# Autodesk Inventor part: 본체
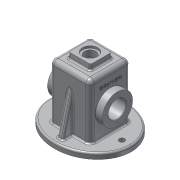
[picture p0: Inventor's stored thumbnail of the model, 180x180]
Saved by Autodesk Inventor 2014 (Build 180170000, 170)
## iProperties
Created: 2017-07
Part Number: 본체
Material: Aluminum 6061
Document SubType Name: Modeling
Designer: user
Density: 2.71 g/cm^3
Appearance: Aluminum - Flat
Mass: 887.783 g
Surface Area: 995.339 cm^2
Volume: 327.595 cm^3
Author: user
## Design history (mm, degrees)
sketch "Sketch1" dims "d0" = 75, "d1" = 65
  geometry: 2 further points; 1 other entity
  constraints: 1 coincident, 2 other
extrude "Extrusion1" new body sketch "Sketch1" distance "d2" = 10; taper "d3" = 0 deg
sketch "Sketch2"
  geometry: L1 (37, -37)-(-37, -37); L2 (-37, -37)-(-37, 37); L3 (-37, 37)-(37, 37); L4 (37, 37)-(37, -37); L5 (37, -37)-(-37, 37); L6 (-37, -37)-(37, 37); 1 further point; 1 other entity
  constraints: 12 end point, 2 midpoint, 2 parallel, 1 horizontal, 1 perpendicular, 1 other
  dimensions: "d4" = 74 distance of L2.end L3.end; "d5" = 74 distance of L1.end L2.end
extrude "Extrusion2" join sketch "Sketch2" distance "d6" = 100; taper "d7" = 0 deg
sketch "Sketch3"
  geometry: L1 (37, 82.194)-(55, 10); L2 (37, 10)-(37, 110) reference; L3 (65, 10)-(-65, 10) reference; L4 (37, 82.194)-(37, 10); L5 (37, 10)-(55, 10); L6 (65, 10)-(65, 80); 1 further point
  constraints: 8 end point, 1 perpendicular
  dimensions: "d8" = 0 distance from line of L2 L1.start; "d9" = 0 distance from line of L3 L1.end; "d10" = 10 distance of L3.start L1.end; "d11" = 14 deg angle of L6 L1; "d12" = 70 distance from line of L6.end L3
extrude "Extrusion3" join sketch "Sketch3" stored distance "d13" = 10; taper "d14" = 0 deg
mirror "Mirror1"
sketch "Sketch4"
  geometry: L1 (10, -28)-(10, 102) reference; C1 r 27.5 at (-45, 37); 1 further point
  constraints: 1 centre point
  dimensions: "d15" = 55 distance from line of L1 C1.centre; "d16" = 55 diameter of C1
extrude "Extrusion4" join sketch "Sketch4" distance "d17" = 13; taper "d18" = 0 deg
sketch "Sketch5"
  geometry: C1 r 27.5 at (0, 0) reference; C2 r 16 at (0, 0); 1 further point
  constraints: 1 centre point, 1 coincident
  dimensions: "d19" = 32 diameter of C2
extrude "Extrusion5" cut sketch "Sketch5" stored distance "d20" = 13; taper "d21" = 0 deg
sketch "Sketch6" dims "d22" = 45
  geometry: L1 (-1.635, 0)-(-22.5, 0); C1 r 27.5 at (0, 0) reference; 3 further points
  constraints: 2 coincident, 2 end point, 1 horizontal, 1 horizontal alignment, 2 other
hole "Hole1" sketch "Sketch6" at (-22.5, 0) diameter "d23" = 3.242; stored, may be unused: countersink angle "d27" = 90 deg, drill point angle "d29" = 118 deg; dims "d24" = 8, "d25" = 4, "d26" = 2, "d28" = 10
pattern_circular "Circular Pattern1" dims angle "d31" = 360 deg
mirror "Mirror2"
sketch "Sketch7"
  geometry: L1 (20, -20)-(-20, -20); L2 (-20, -20)-(-20, 20); L3 (-20, 20)-(20, 20); L4 (20, 20)-(20, -20); L5 (20, -20)-(-20, 20); L6 (-20, -20)-(20, 20); 1 further point
  constraints: 12 end point, 2 midpoint, 2 parallel, 1 horizontal, 1 perpendicular
  dimensions: "d33" = 40 distance of L2.end L3.end; "d34" = 40 distance of L1.end L2.end
extrude "Extrusion6" join sketch "Sketch7" distance "d35" = 10; taper "d36" = 0 deg
sketch "Sketch8"
  geometry: L1 (32, -32)-(-32, -32); L2 (-32, -32)-(-32, 32); L3 (-32, 32)-(32, 32); L4 (32, 32)-(32, -32); L5 (32, -32)-(-32, 32); L6 (-32, -32)-(32, 32); 1 further point; 1 other entity
  constraints: 12 end point, 2 midpoint, 2 parallel, 1 horizontal, 1 perpendicular, 1 other
  dimensions: "d37" = 64 distance of L2.end L3.end; "d38" = 64 distance of L1.end L2.end
extrude "Extrusion7" cut sketch "Sketch8" distance "d39" = 105; taper "d40" = 0 deg
sketch "Sketch9"
  geometry: L1 (50, 55)-(-50, 55); L2 (50, 71)-(50, 39) reference; L3 (-50, 39)-(-50, 71) reference; L4 (-25, 71)-(-25, 75.5); L5 (-32, 0)-(-32, 105) reference; L6 (-25, 75.5)-(-32, 82.5); L7 (-25, 71)-(-32, 71); L8 (-32, 71)-(-32, 82.5); L9 (0, 55)-(0, 87.906); L10 (25, 71)-(25, 75.5); L11 (32, 0)-(32, 105); L12 (25, 75.5)-(32, 82.5); L13 (25, 71)-(32, 71); L14 (32, 71)-(32, 82.5); 2 further points
  constraints: 22 end point, 6 symmetric about line, 4 point on line, 2 midpoint, 2 parallel, 1 coincident, 1 collinear, 1 horizontal, 1 perpendicular
  dimensions: "d41" = 0 distance from line of L1.start L2; "d42" = 0 distance from line of L3 L1.end; "d43" = 7 distance between parallel lines of L4 L5; "d44" = 135 deg angle of L5 L6; "d45" = 55 diameter of L6.end L1; "d46" = 32 diameter of L7 L1; "d47" = 16.90632 distance from line of L9.end L7
revolve "Revolution1" sketch "Sketch9" stored, may be unused: angle "d48" = 90 deg
sketch "Sketch10"
  geometry: C1 r 14 at (0, 0); 1 further point
  constraints: 1 centre point, 1 coincident
  dimensions: "d49" = 28 diameter of C1
extrude "Extrusion8" cut sketch "Sketch10" distance "d50" = 4; taper "d51" = 0 deg
sketch "Sketch11"
  geometry: C1 r 14 at (0, 0) reference; C2 r 10.5 at (0, 0)
  constraints: 1 centre point, 1 coincident
  dimensions: "d52" = 21 diameter of C2
extrude "Extrusion9" cut sketch "Sketch11" stored distance "d53" = 4; taper "d54" = 0 deg
sketch "Sketch12"
  geometry: L1 (37, 37)-(37, -37) reference; C1 r 5 at (-58, 0); C2 r 5 at (58, 0); 1 further point; 1 other entity
  constraints: 2 centre point, 1 horizontal alignment, 1 other
  dimensions: "d55" = 10 diameter of C2; "d56" = 10 diameter of C1; "d57" = 58 distance of point (0, 0) C1.centre; "d58" = 116 distance of C2.centre C1.centre; "d59" = 21 distance from line of C2.centre L1
extrude "Extrusion10" cut sketch "Sketch12" stored distance "d60" = 4; taper "d61" = 0 deg
fillet "Fillet1" dims "d62" = 3
fillet "Fillet2" dims "d63" = 3
fillet "Fillet3" dims "d64" = 8
fillet "Fillet4" dims "d65" = 8
fillet "Fillet7" dims "d68" = 0.5
fillet "Fillet8" dims "d69" = 0.5
fillet "Fillet9" dims "d70" = 3
fillet "Fillet10" dims "d71" = 3
sketch "Sketch13"
  geometry: L1 (-10, 0)-(-10, 40) reference; L2 (0, 0)-(-10, 0) reference; L3 (0, 0)-(-10, 0.875); L4 (8, -17)-(97, -17) reference; L5 (0, 40)-(-10, 39.125); L6 (97, 57)-(8, 57) reference; L7 (0, 0)-(-10, 0); L8 (-10, 0)-(-10, 0.875); L9 (0, 40)-(-10, 40); L10 (-10, 40)-(-10, 39.125); 1 further point
  constraints: 12 end point, 3 point on line, 2 collinear, 2 perpendicular
  dimensions: "d72" = 5 deg angle of L3 L4; "d73" = 5 deg angle of L6 L5
extrude "Extrusion11" cut sketch "Sketch13" stored distance "d74" = 4; taper "d75" = 0 deg
chamfer "Chamfer1" distance "d76" = 1; stored, may be unused: second distance "d77" = 2, angle "d78" = 45 deg
fillet "Fillet11" dims "d79" = 3
fillet "Fillet12" dims "d80" = 3
workplane "Work Plane1"
sketch "Sketch14"
  geometry: L1 (-18, 12.886)-(-18, 45.114) reference; C1 r 16 at (47, 29) reference; 2 further points
  constraints: 1 other
  dimensions: "d82" = 30 distance from line of L1 point (12, 29); "d83" = 0 vertical distance of point (12, 29) C1.centre
emboss "Emboss1" sketch "Sketch14" dims "d0" = 75, "d1" = 65, "d8" = 0, "d9" = 0, "d10" = 10, "d11" = 14 deg, "d12" = 70, "d84" = 0.5, "d85" = 0
fillet "Fillet13" dims "d86" = 3
fillet "Fillet14" dims "d87" = 3
body "Solid1"
other parameters: "d81" = 77
